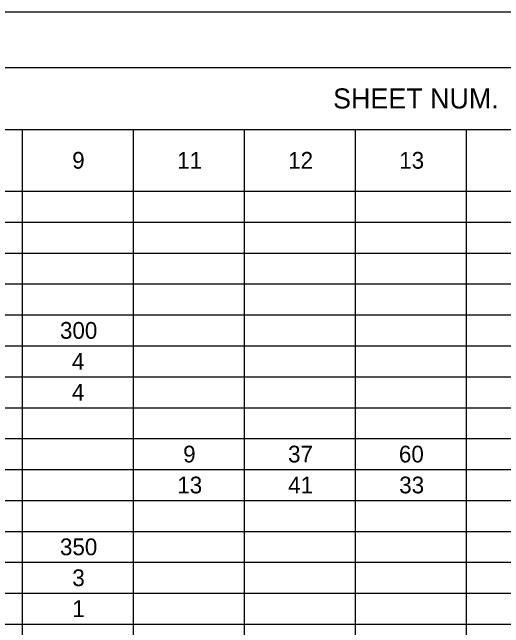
# Model space of a CAD drawing. Extents: x 0 to 34, y 0 to 22.
# Drawn here: x 4.43 to 8.87, y 16.43 to 22 of the extents above; entities that cross this region are included whole.
import ezdxf

# ---------------------------------------------------------------- set-up
doc = ezdxf.new("R2010")
doc.units = 0
for name, color, linetype in [('SH_Border', 7, 'Continuous'), ('SH_Cut_Line', 7, 'Continuous'), ('SH_Text', 7, 'Continuous')]:
    doc.layers.add(name, color=color, linetype=linetype)

msp = doc.modelspace()

# ---------------------------------------------------------------- linework, layer by layer
at = {"layer": 'SH_Border'}
msp.add_lwpolyline([(1.5, 21.5), (33.5, 21.5), (33.5, 0.5), (1.5, 0.5)], close=True, dxfattribs=at)
at = {"layer": 'SH_Cut_Line'}
msp.add_lwpolyline([(0, 0), (34, 0), (34, 22), (0, 22)], close=True, dxfattribs=at)
at = {"layer": 'SH_Text'}
for p, q in [((1.5, 21.5), (32, 21.5)), ((1.5, 20.94), (15.5643, 20.94)), ((4.5138, 20.94), (4.5138, 0.5)), ((5.5184, 20.94), (5.5184, 0.5)), ((6.5229, 20.94), (6.5229, 0.5)), ((7.5275, 20.94), (7.5275, 0.5)), ((8.5321, 20.94), (8.5321, 0.5)), ((1.5, 20.38), (32, 20.38)), ((1.5, 20.1), (32, 20.1)), ((1.5, 19.82), (32, 19.82)), ((1.5, 19.54), (32, 19.54)), ((1.5, 19.26), (32, 19.26)), ((1.5, 18.98), (32, 18.98)), ((1.5, 18.7), (32, 18.7)), ((1.5, 18.42), (32, 18.42)), ((1.5, 18.14), (32, 18.14)), ((1.5, 17.86), (32, 17.86)), ((1.5, 17.58), (32, 17.58)), ((1.5, 17.3), (32, 17.3)), ((1.5, 17.02), (32, 17.02)), ((1.5, 16.74), (32, 16.74)), ((1.5, 16.46), (32, 16.46))]:
    msp.add_line(p, q, dxfattribs=at)

# ---------------------------------------------------------------- texts
for s, height, p in [('SHEET NUM.', 0.18184, (7.3288, 21.1291)), ('9', 0.1515, (4.9671, 20.5842)), ('11', 0.15153, (5.9176, 20.5842)), ('12', 0.15153, (6.9224, 20.5842)), ('13', 0.15153, (7.9275, 20.5842)), ('300', 0.15153, (4.8565, 19.0442)), ('4', 0.1515, (4.9647, 18.7642)), ('4', 0.1515, (4.9647, 18.4842)), ('9', 0.1515, (5.9717, 17.9242)), ('37', 0.15153, (6.9213, 17.9242)), ('60', 0.15153, (7.9247, 17.9242)), ('13', 0.15153, (5.9184, 17.6442)), ('41', 0.15153, (6.9222, 17.6442)), ('33', 0.15153, (7.9275, 17.6442)), ('350', 0.15153, (4.8565, 17.0842)), ('3', 0.1515, (4.9682, 16.8042)), ('1', 0.1515, (4.9675, 16.5242))]:
    msp.add_text(s, height=height, dxfattribs=at).set_placement(p)

doc.saveas('drawing.dxf')
